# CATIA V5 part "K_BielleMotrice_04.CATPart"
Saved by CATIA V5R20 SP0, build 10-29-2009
Part number: Bielle_motrice_04
Bounding box of the stored display mesh (mm): x -195 to -75, y -177.303 to -162.303, z -65 to -35
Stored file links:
  G:\Khaled_CFAO_2011\ST2M\ST2M_GR2\jcoetard\Khaled\CAD_CATIA\K_BielleMotrice_04.CATPart
  J:\Thinkmotion\Thinkmotion_COETARD\Maquette_catia\Maquette_catia_R20_Licence_education\jcharlescoetard.CATPRODUCT\Assemblage_Pince_Prehension_Mors_Paralleles.CATProduct
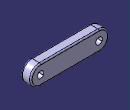
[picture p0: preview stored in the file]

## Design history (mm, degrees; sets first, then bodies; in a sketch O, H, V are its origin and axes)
Set1
  Plane1 "Plan_bielle_motrice_02": linked copy from another document
  Point1 "Point.11": linked copy from another document
  Point2 "Point.12": linked copy from another document
Body1 (main body)
  Sketch1 on Plane1, origin (0, -162.303, 0), H (-1, 0, 0), V (0, 0, 1)
    construction line L1 (90, -50) -> (180, -50)
    point P1 (90, -50)
    point P2 (180, -50)
    line L2 (90, -35) -> (180, -35)
    line L3 (180, -65) -> (90, -65)
    arc A1 centre (180, -50) radius 15 from (180, -35) to (180, -65) cw
    arc A2 centre (90, -50) radius 15 from (90, -65) to (90, -35) cw
    reference projected point E1 (90, -50) from Point1
    reference projected point E2 (180, -50) from Point2
    distance L2 L3 = 30
    horizontal: L1 H
    tangency: A1 L2, A2 L2, A1 L3, A2 L3
    coincidence: E1 P1, E2 P2
  Pad1: profile Sketch1, direction (0, -1, 0), length 15
  Sketch2 on start face of Pad1, origin (-90, -162.303, -66.6667), H (1, 0, 0), V (0, 0, -1)
    point P1 (0, -16.6667)
    reference projected point E1 (0, -16.6667) from Point1
    coincidence: E1 P1
  Hole1: placed by Sketch2, at (-90, -162.303, -50) direction (0, -1, 0), diameter 10, depth 20
  Sketch3 on start face of Pad1, origin (-180, -162.303, -66.6667), H (1, 0, 0), V (0, 0, -1)
    point P1 (0, -16.6667)
    reference projected point E1 (0, -16.6667) from Point2
    coincidence: E1 P1
  Hole2: placed by Sketch3, at (-180, -162.303, -50) direction (0, -1, 0), diameter 10, depth 20
  Fillet1: radius 2, on end face of Pad1; edge [face of Pad1 from Sketch1.A1 | start face of Pad1]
